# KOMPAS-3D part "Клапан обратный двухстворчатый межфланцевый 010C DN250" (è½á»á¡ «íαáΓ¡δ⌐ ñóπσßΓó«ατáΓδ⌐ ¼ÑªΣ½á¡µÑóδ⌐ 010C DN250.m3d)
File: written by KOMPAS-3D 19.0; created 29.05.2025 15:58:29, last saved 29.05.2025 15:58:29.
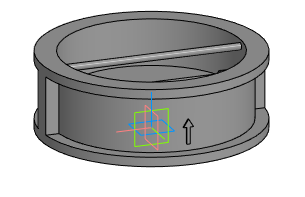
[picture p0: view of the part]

Document properties: Полное имя файла: E:\Dendor Работа Сачек\3D для проекитирвщиков\5.2 Тип 010C, 010C.Y Клапан обратный двухстворчатый межфланцевый\stp_Клапан обратный двухстворчатый межфланцевый 010C\Клапан обратный двухстворчатый межфланцевый 010C DN250.m3d

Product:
- Part/product: Клапан обратный двухстворчатый межфланцевый 010C DN250

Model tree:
1. Операция без истории:1  (labels: Клапан обратный двухстворчатый межфланцевый 010C DN250)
